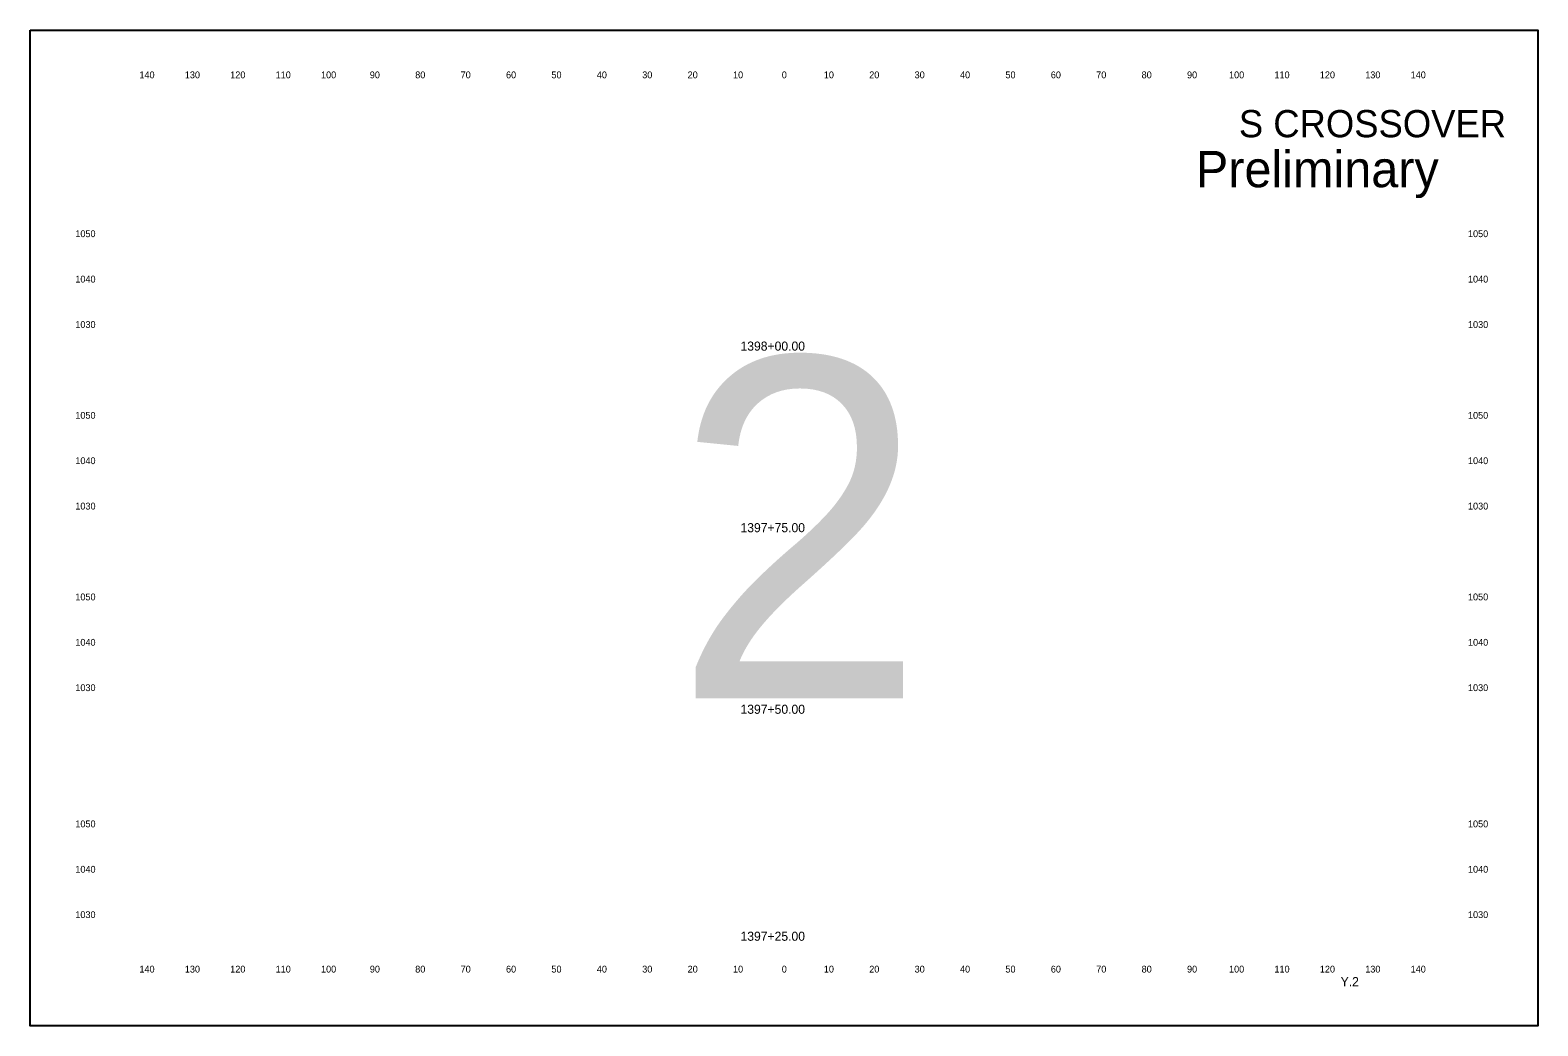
# Model space of a CAD drawing. Extents: x 10123 to 14768, y 9730 to 9950.
# Drawn here: x 10483.2 to 10815.3, y 9730.3 to 9949.6 of the extents above; entities that cross this region are included whole.
import ezdxf

# ---------------------------------------------------------------- set-up
doc = ezdxf.new("R2010")
doc.units = 0
for name, color, linetype in [('dsnTextCpn', 7, 'Continuous'), ('dsnTextCpnTitleSheetLocDesc', 7, 'Continuous'), ('dsnTextCpnTitleSheetPIN', 7, 'Continuous'), ('dsnTextCpnTitleSheetWorkType', 7, 'Continuous')]:
    doc.layers.add(name, color=color, linetype=linetype)

msp = doc.modelspace()

# ---------------------------------------------------------------- linework, layer by layer
at = {"layer": 'dsnTextCpnTitleSheetWorkType'}
msp.add_lwpolyline([(10483.21, 9949.6), (10815.29, 9949.6), (10815.29, 9730.26), (10483.21, 9730.26)], close=True, dxfattribs=at)

# ---------------------------------------------------------------- texts
at = {"layer": 'dsnTextCpn'}
for s, height, p in [('140', 1.5, (10507.27, 9939)), ('130', 1.5, (10517.27, 9939)), ('120', 1.5, (10527.27, 9939)), ('110', 1.5, (10537.27, 9939)), ('100', 1.5, (10547.27, 9939)), ('90', 1.5, (10558.02, 9939)), ('80', 1.5, (10568.02, 9939)), ('70', 1.5, (10578.02, 9939)), ('60', 1.5, (10588.02, 9939)), ('50', 1.5, (10598.02, 9939)), ('40', 1.5, (10608.02, 9939)), ('30', 1.5, (10618.02, 9939)), ('20', 1.5, (10628.02, 9939)), ('10', 1.5, (10638.02, 9939)), ('0', 1.5, (10648.76, 9939)), ('0', 1.5, (10648.76, 9939)), ('10', 1.5, (10658.02, 9939)), ('20', 1.5, (10668.02, 9939)), ('30', 1.5, (10678.02, 9939)), ('40', 1.5, (10688.02, 9939)), ('50', 1.5, (10698.02, 9939)), ('60', 1.5, (10708.02, 9939)), ('70', 1.5, (10718.02, 9939)), ('80', 1.5, (10728.02, 9939)), ('90', 1.5, (10738.02, 9939)), ('100', 1.5, (10747.27, 9939)), ('110', 1.5, (10757.27, 9939)), ('120', 1.5, (10767.27, 9939)), ('130', 1.5, (10777.27, 9939)), ('140', 1.5, (10787.27, 9939)), ('S CROSSOVER', 6, (10749.44, 9926)), ('1050', 1.5, (10493.15, 9904)), ('1050', 1.5, (10799.9, 9904)), ('1040', 1.5, (10493.15, 9894)), ('1040', 1.5, (10799.9, 9894)), ('1030', 1.5, (10493.15, 9884)), ('1030', 1.5, (10799.9, 9884)), ('1398+00.00', 2, (10639.67, 9879)), ('1050', 1.5, (10493.15, 9864)), ('1050', 1.5, (10799.9, 9864)), ('1040', 1.5, (10493.15, 9854)), ('1040', 1.5, (10799.9, 9854)), ('1030', 1.5, (10493.15, 9844)), ('1030', 1.5, (10799.9, 9844)), ('1397+75.00', 2, (10639.67, 9839)), ('1050', 1.5, (10493.15, 9824)), ('1050', 1.5, (10799.9, 9824)), ('1040', 1.5, (10493.15, 9814)), ('1040', 1.5, (10799.9, 9814)), ('1030', 1.5, (10493.15, 9804)), ('1030', 1.5, (10799.9, 9804)), ('1397+50.00', 2, (10639.67, 9799)), ('1050', 1.5, (10493.15, 9774)), ('1050', 1.5, (10799.9, 9774)), ('1040', 1.5, (10493.15, 9764)), ('1040', 1.5, (10799.9, 9764)), ('1030', 1.5, (10493.15, 9754)), ('1030', 1.5, (10799.9, 9754)), ('1397+25.00', 2, (10639.67, 9749)), ('140', 1.5, (10507.27, 9742)), ('130', 1.5, (10517.27, 9742)), ('120', 1.5, (10527.27, 9742)), ('110', 1.5, (10537.27, 9742)), ('100', 1.5, (10547.27, 9742)), ('90', 1.5, (10558.02, 9742)), ('80', 1.5, (10568.02, 9742)), ('70', 1.5, (10578.02, 9742)), ('60', 1.5, (10588.02, 9742)), ('50', 1.5, (10598.02, 9742)), ('40', 1.5, (10608.02, 9742)), ('30', 1.5, (10618.02, 9742)), ('20', 1.5, (10628.02, 9742)), ('10', 1.5, (10638.02, 9742)), ('0', 1.5, (10648.76, 9742)), ('0', 1.5, (10648.76, 9742)), ('10', 1.5, (10658.02, 9742)), ('20', 1.5, (10668.02, 9742)), ('30', 1.5, (10678.02, 9742)), ('40', 1.5, (10688.02, 9742)), ('50', 1.5, (10698.02, 9742)), ('60', 1.5, (10708.02, 9742)), ('70', 1.5, (10718.02, 9742)), ('80', 1.5, (10728.02, 9742)), ('90', 1.5, (10738.02, 9742)), ('100', 1.5, (10747.27, 9742)), ('110', 1.5, (10757.27, 9742)), ('120', 1.5, (10767.27, 9742)), ('130', 1.5, (10777.27, 9742)), ('140', 1.5, (10787.27, 9742))]:
    msp.add_text(s, height=height, dxfattribs=at).set_placement(p)
at = {"layer": 'dsnTextCpnTitleSheetLocDesc'}
msp.add_text('Preliminary', height=8, dxfattribs=at).set_placement((10739.97, 9915))
at = {"layer": 'dsnTextCpnTitleSheetPIN'}
msp.add_text('Y.2', height=2, dxfattribs=at).set_placement((10771.86, 9739))
at = {"layer": 'dsnTextCpnTitleSheetWorkType'}
msp.add_text('2', height=75, dxfattribs=at).set_placement((10624.72, 9802.43))

doc.saveas('drawing.dxf')
